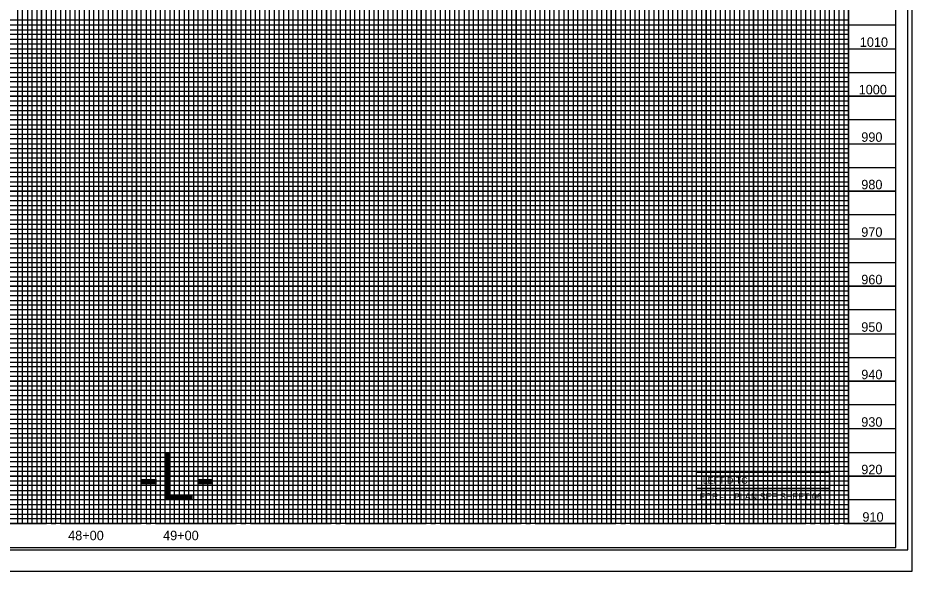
# Model space of a CAD drawing. Extents: x 1263639 to 1265460, y 747271 to 748371.
# Drawn here: x 1264381 to 1265323, y 747271 to 747853 of the extents above; entities that cross this region are included whole.
import ezdxf

# ---------------------------------------------------------------- set-up
doc = ezdxf.new("R2010")
doc.units = 0
for name, color, linetype in [('Pattern 1', 7, 'Continuous'), ('Pattern 2', 7, 'Continuous'), ('Prop Approach Slab', 7, 'Continuous'), ('Prop Drainage Structure Bridge Opening', 7, 'Continuous'), ('Prop Erosion Rip Rap Single Stone CELL', 7, 'Continuous'), ('Prop Grid Mask', 7, 'Continuous'), ('Prop Horizontal Alignment Curve and Spiral Data', 7, 'Continuous'), ('Prop Paved Shoulder', 7, 'Continuous'), ('Prop PFL Text', 7, 'Continuous'), ('Prop Terminator CELL', 7, 'Continuous'), ('Prop Vertical Profile Strip Grade', 7, 'Continuous'), ('Prop VPI Label', 7, 'Continuous'), ('Sheet Border Standard 30in CELL', 7, 'Continuous'), ('Sheet Profile Grid Middle CELL', 7, 'Continuous'), ('Sheet Sticker Exception Certification CELL', 7, 'Continuous')]:
    doc.layers.add(name, color=color, linetype=linetype)

msp = doc.modelspace()

# ---------------------------------------------------------------- linework, layer by layer
at = {"layer": 'Pattern 1'}
for points in [[(1264355.75, 747320.74), (1264405.75, 747320.74), (1264405.75, 748345.74)], [(1264455.75, 748345.74), (1264455.75, 747320.74), (1264505.75, 747320.74), (1264505.75, 748345.74)], [(1264555.75, 748345.74), (1264555.75, 747320.74), (1264605.75, 747320.74), (1264605.75, 748345.74)], [(1264655.75, 748345.74), (1264655.75, 747320.74), (1264705.75, 747320.74), (1264705.75, 748345.74)], [(1264755.75, 748345.74), (1264755.75, 747320.74), (1264805.75, 747320.74), (1264805.75, 748345.74)], [(1264855.75, 748345.74), (1264855.75, 747320.74), (1264905.75, 747320.74), (1264905.75, 748345.74)], [(1264955.75, 748345.74), (1264955.75, 747320.74), (1265005.75, 747320.74), (1265005.75, 748295.74)], [(1265055.75, 748295.74), (1265055.75, 747320.74), (1265105.75, 747320.74), (1265105.75, 748295.74)], [(1265155.75, 748184.69), (1265155.75, 747320.74), (1265205.75, 747320.74), (1265205.75, 748184.69)], [(1265255.75, 748184.69), (1265255.75, 747320.74), (1265305.75, 747320.74)], [(1265305.75, 747770.74), (1263805.75, 747770.74), (1263805.75, 747820.74), (1265305.75, 747820.74)], [(1265305.75, 747670.74), (1263805.75, 747670.74), (1263805.75, 747720.74), (1265305.75, 747720.74)], [(1265305.75, 747570.74), (1263805.75, 747570.74), (1263805.75, 747620.74), (1265305.75, 747620.74)], [(1265305.75, 747470.74), (1263805.75, 747470.74), (1263805.75, 747520.74), (1265305.75, 747520.74)], [(1265305.75, 747370.74), (1263805.75, 747370.74), (1263805.75, 747420.74), (1265305.75, 747420.74)]]:
    msp.add_lwpolyline(points, dxfattribs=at)
at = {"layer": 'Pattern 2'}
for points in [[(1264330.75, 747320.74), (1264380.75, 747320.74), (1264380.75, 748345.74)], [(1264430.75, 748345.74), (1264430.75, 747320.74), (1264480.75, 747320.74), (1264480.75, 748345.74)], [(1264530.75, 748345.74), (1264530.75, 747320.74), (1264580.75, 747320.74), (1264580.75, 748345.74)], [(1264630.75, 748345.74), (1264630.75, 747320.74), (1264680.75, 747320.74), (1264680.75, 748345.74)], [(1264730.75, 748345.74), (1264730.75, 747320.74), (1264780.75, 747320.74), (1264780.75, 748345.74)], [(1264830.75, 748345.74), (1264830.75, 747320.74), (1264880.75, 747320.74), (1264880.75, 748345.74)], [(1264930.75, 748345.74), (1264930.75, 747320.74), (1264980.75, 747320.74), (1264980.75, 748345.74)], [(1265030.75, 748295.74), (1265030.75, 747320.74), (1265080.75, 747320.74), (1265080.75, 748295.74)], [(1265130.75, 748184.69), (1265130.75, 747320.74), (1265180.75, 747320.74), (1265180.75, 748184.69)], [(1265230.75, 748184.69), (1265230.75, 747320.74)], [(1265305.75, 747845.74), (1263805.75, 747845.74), (1263805.75, 747795.74), (1265305.75, 747795.74)], [(1265305.75, 747745.74), (1263805.75, 747745.74), (1263805.75, 747695.74), (1265305.75, 747695.74)], [(1265305.75, 747645.74), (1263805.75, 747645.74), (1263805.75, 747595.74), (1265305.75, 747595.74)], [(1265305.75, 747545.74), (1263805.75, 747545.74), (1263805.75, 747495.74), (1265305.75, 747495.74)], [(1265305.75, 747445.74), (1263805.75, 747445.74), (1263805.75, 747395.74), (1265305.75, 747395.74)], [(1265305.75, 747345.74), (1263805.75, 747345.74)]]:
    msp.add_lwpolyline(points, dxfattribs=at)
at = {"layer": 'Prop Approach Slab'}
msp.add_line((1265157.4, 747366.24), (1265230.39, 747366.24), dxfattribs=at)
at = {"layer": 'Prop Drainage Structure Bridge Opening'}
msp.add_line((1263638.75, 747270.74), (1265322.75, 747270.74), dxfattribs=at)
at = {"layer": 'Prop Erosion Rip Rap Single Stone CELL'}
msp.add_lwpolyline([(1265095.75, 747374.74), (1265235.75, 747374.74), (1265235.75, 747357.74), (1265095.75, 747357.74)], close=True, dxfattribs=at)
at = {"layer": 'Prop Grid Mask'}
msp.add_lwpolyline([(1263855.75, 748345.74), (1265105.7, 748345.74), (1265105.75, 747320.74), (1263855.75, 747320.74)], close=True, dxfattribs=at)
at = {"layer": 'Prop Paved Shoulder'}
msp.add_line((1265305.75, 747320.74), (1263805.75, 747320.74), dxfattribs=at)
msp.add_lwpolyline([(1265305.75, 748345.74), (1263805.75, 748345.74), (1263805.75, 747295.74), (1265305.75, 747295.74)], close=True, dxfattribs=at)
at = {"layer": 'Prop PFL Text'}
for p, q in [((1264405.75, 748345.74), (1264405.75, 747320.74)), ((1264455.75, 748345.74), (1264455.75, 747320.74)), ((1264505.75, 748345.74), (1264505.75, 747320.74)), ((1264555.75, 748345.74), (1264555.75, 747320.74)), ((1264605.75, 748345.74), (1264605.75, 747320.74)), ((1264655.75, 748345.74), (1264655.75, 747320.74)), ((1264705.75, 748345.74), (1264705.75, 747320.74)), ((1264755.75, 748345.74), (1264755.75, 747320.74)), ((1264805.75, 748345.74), (1264805.75, 747320.74)), ((1264855.75, 748345.74), (1264855.75, 747320.74)), ((1264905.75, 748345.74), (1264905.75, 747320.74)), ((1264955.75, 748345.74), (1264955.75, 747320.74)), ((1265005.75, 748345.74), (1265005.75, 747320.74)), ((1265055.75, 748295.74), (1265055.75, 747320.74)), ((1265105.75, 747320.74), (1265105.75, 748208.19)), ((1265155.75, 747320.74), (1265155.75, 748184.69)), ((1265205.75, 747320.74), (1265205.75, 748184.69)), ((1265255.75, 747320.74), (1265255.75, 748184.69)), ((1263805.75, 747820.74), (1265305.75, 747820.74)), ((1263805.75, 747770.74), (1265305.75, 747770.74)), ((1263805.75, 747720.74), (1265305.75, 747720.74)), ((1263805.75, 747670.74), (1265305.75, 747670.74)), ((1263805.75, 747620.74), (1265305.75, 747620.74)), ((1263805.75, 747570.74), (1265305.75, 747570.74)), ((1263805.75, 747520.74), (1265305.75, 747520.74)), ((1263805.75, 747470.74), (1265305.75, 747470.74)), ((1263805.75, 747420.74), (1265305.75, 747420.74)), ((1263805.75, 747370.74), (1265305.75, 747370.74))]:
    msp.add_line(p, q, dxfattribs=at)
at = {"layer": 'Prop Terminator CELL'}
msp.add_lwpolyline([(1265318.25, 748348.29), (1263651.75, 748348.29), (1263651.75, 747293.19), (1265318.25, 747293.19)], close=True, dxfattribs=at)
at = {"layer": 'Prop VPI Label'}
msp.add_lwpolyline([(1265322.75, 748370.74), (1263638.75, 748370.74), (1263638.75, 747270.74), (1265322.75, 747270.74)], close=True, dxfattribs=at)
at = {"layer": 'Sheet Profile Grid Middle CELL'}
msp.add_lwpolyline([(1265095.75, 747357.74), (1265235.75, 747357.74), (1265235.75, 747340.74), (1265095.75, 747340.74)], close=True, dxfattribs=at)
at = {"layer": 'Sheet Sticker Exception Certification CELL'}
for points in [[(1264385.75, 747320.74), (1264385.75, 748345.74)], [(1264390.75, 748345.74), (1264390.75, 747320.74), (1264395.75, 747320.74), (1264395.75, 748345.74)], [(1264400.75, 748345.74), (1264400.75, 747320.74), (1264410.75, 747320.74), (1264410.75, 748345.74)], [(1264415.75, 748345.74), (1264415.75, 747320.74), (1264415.75, 747320.74), (1264420.75, 747320.74), (1264420.75, 748345.74)], [(1264425.75, 748345.74), (1264425.75, 747320.74), (1264435.75, 747320.74), (1264435.75, 748345.74)], [(1264440.75, 748345.74), (1264440.75, 747320.74), (1264445.75, 747320.74), (1264445.75, 748345.74)], [(1264450.75, 748345.74), (1264450.75, 747320.74), (1264460.75, 747320.74), (1264460.75, 748345.74)], [(1264465.75, 748345.74), (1264465.75, 747320.74), (1264470.75, 747320.74), (1264470.75, 748345.74)], [(1264475.75, 748345.74), (1264475.75, 747320.74), (1264485.75, 747320.74), (1264485.75, 748345.74)], [(1264490.75, 748345.74), (1264490.75, 747320.74), (1264495.75, 747320.74), (1264495.75, 748345.74)], [(1264500.75, 748345.74), (1264500.75, 747320.74), (1264510.75, 747320.74), (1264510.75, 748345.74)], [(1264515.75, 748345.74), (1264515.75, 747320.74), (1264520.75, 747320.74), (1264520.75, 748345.74)], [(1264525.75, 748345.74), (1264525.75, 747320.74), (1264535.75, 747320.74), (1264535.75, 748345.74)], [(1264540.75, 748345.74), (1264540.75, 747320.74), (1264545.75, 747320.74), (1264545.75, 748345.74)], [(1264550.75, 748345.74), (1264550.75, 747320.74), (1264560.75, 747320.74), (1264560.75, 748345.74)], [(1264565.75, 748345.74), (1264565.75, 747320.74)], [(1264565.75, 747320.74), (1264570.75, 747320.74), (1264570.75, 748345.14)], [(1264575.75, 748345.14), (1264575.75, 747320.74), (1264585.75, 747320.74), (1264585.75, 748345.74)], [(1264590.75, 748345.74), (1264590.75, 747320.74), (1264595.75, 747320.74), (1264595.75, 748345.74)], [(1264600.75, 748345.74), (1264600.75, 747320.74), (1264610.75, 747320.74), (1264610.75, 748345.74)], [(1264615.75, 748345.74), (1264615.75, 747320.74), (1264620.75, 747320.74), (1264620.75, 748345.74)], [(1264625.75, 748345.74), (1264625.75, 747320.74), (1264635.75, 747320.74), (1264635.75, 748345.74)], [(1264640.75, 748345.74), (1264640.75, 747320.74), (1264645.75, 747320.74), (1264645.75, 748345.74)], [(1264650.75, 748345.74), (1264650.75, 747320.74), (1264660.75, 747320.74), (1264660.75, 748345.74)], [(1264665.75, 748345.74), (1264665.75, 747320.74), (1264670.75, 747320.74), (1264670.75, 748345.74)], [(1264675.75, 748345.74), (1264675.75, 747320.74), (1264685.75, 747320.74), (1264685.75, 748345.74)], [(1264690.75, 748345.74), (1264690.75, 747320.74), (1264695.75, 747320.74), (1264695.75, 748345.74)], [(1264700.75, 748345.74), (1264700.75, 747320.74), (1264710.75, 747320.74), (1264710.75, 748345.74)], [(1264715.75, 748345.74), (1264715.75, 747320.74), (1264720.75, 747320.74), (1264720.75, 748345.74)], [(1264725.75, 748345.74), (1264725.75, 747320.74), (1264735.75, 747320.74), (1264735.75, 748345.74)], [(1264740.75, 748345.74), (1264740.75, 747320.74), (1264745.75, 747320.74), (1264745.75, 748345.74)], [(1264750.75, 748345.74), (1264750.75, 747320.74), (1264760.75, 747320.74), (1264760.75, 748345.74)], [(1264765.75, 748345.74), (1264765.75, 747320.74), (1264770.75, 747320.74), (1264770.75, 748345.74)], [(1264775.75, 748345.74), (1264775.75, 747320.74), (1264785.75, 747320.74), (1264785.75, 748345.74)], [(1264790.75, 748345.74), (1264790.75, 747320.74), (1264795.75, 747320.74), (1264795.75, 748345.74)], [(1264800.75, 748345.74), (1264800.75, 747320.74), (1264810.75, 747320.74), (1264810.75, 748345.74)], [(1264815.75, 748345.74), (1264815.75, 747320.74), (1264820.75, 747320.74), (1264820.75, 748345.74)], [(1264825.75, 748345.74), (1264825.75, 747320.74), (1264835.75, 747320.74), (1264835.75, 748345.74)], [(1264840.75, 748345.74), (1264840.75, 747320.74), (1264845.75, 747320.74), (1264845.75, 748345.74)], [(1264850.75, 748345.74), (1264850.75, 747320.74), (1264860.75, 747320.74), (1264860.75, 748345.74)], [(1264865.75, 748345.74), (1264865.75, 747320.74), (1264870.75, 747320.74), (1264870.75, 748345.74)], [(1264875.75, 748345.74), (1264875.75, 747320.74)], [(1264875.75, 747320.74), (1264885.75, 747320.74), (1264885.75, 748345.74)], [(1264890.75, 748345.74), (1264890.75, 747320.74), (1264895.75, 747320.74), (1264895.75, 748345.74)], [(1264900.75, 748345.74), (1264900.75, 747320.74), (1264910.75, 747320.74), (1264910.75, 748345.74)], [(1264915.75, 748345.74), (1264915.75, 747320.74), (1264920.75, 747320.74), (1264920.75, 748345.74)], [(1264925.75, 748345.74), (1264925.75, 747320.74), (1264935.75, 747320.74), (1264935.75, 748345.74)], [(1264940.75, 748345.74), (1264940.75, 747320.74), (1264945.75, 747320.74), (1264945.75, 748345.74)], [(1264950.75, 748345.74), (1264950.75, 747320.74), (1264960.75, 747320.74), (1264960.75, 748345.74)], [(1264965.75, 748345.74), (1264965.75, 747320.74), (1264970.75, 747320.74), (1264970.75, 748345.74)], [(1264975.75, 748345.74), (1264975.75, 747320.74), (1264985.75, 747320.74), (1264985.75, 748345.74)], [(1264990.75, 748345.74), (1264990.75, 747320.74), (1264995.75, 747320.74), (1264995.75, 748345.74)], [(1265000.75, 748345.74), (1265000.75, 747320.74), (1265010.75, 747320.74), (1265010.75, 748295.74)], [(1265015.75, 748295.74), (1265015.75, 747320.74), (1265020.75, 747320.74), (1265020.75, 748295.74)], [(1265025.75, 748295.74), (1265025.75, 747320.74), (1265035.75, 747320.74), (1265035.75, 748295.74)], [(1265040.75, 748295.74), (1265040.75, 747320.74), (1265045.75, 747320.74), (1265045.75, 748295.74)], [(1265050.75, 748295.74), (1265050.75, 747320.74), (1265060.75, 747320.74), (1265060.75, 748295.74)], [(1265065.75, 748295.74), (1265065.75, 747320.74), (1265070.75, 747320.74), (1265070.75, 748295.74)], [(1265075.75, 748295.74), (1265075.75, 747320.74), (1265085.75, 747320.74), (1265085.75, 748295.74)], [(1265090.75, 748295.74), (1265090.75, 747320.74), (1265095.75, 747320.74), (1265095.75, 748295.74)], [(1265100.75, 748295.74), (1265100.75, 747320.74), (1265110.75, 747320.74), (1265110.75, 748184.69)], [(1265115.75, 748184.69), (1265115.75, 747320.74), (1265120.75, 747320.74), (1265120.75, 748184.69)], [(1265125.75, 748184.69), (1265125.75, 747320.74), (1265135.75, 747320.74), (1265135.75, 748184.69)], [(1265140.75, 748184.69), (1265140.75, 747320.74), (1265145.75, 747320.74), (1265145.75, 748184.69)], [(1265150.75, 748184.69), (1265150.75, 747320.74), (1265160.75, 747320.74), (1265160.75, 748184.69)], [(1265165.75, 748184.69), (1265165.75, 747320.74), (1265170.75, 747320.74), (1265170.75, 748184.69)], [(1265175.75, 748184.69), (1265175.75, 747320.74), (1265185.75, 747320.74), (1265185.75, 748184.69)], [(1265190.75, 748184.69), (1265190.75, 747320.74)], [(1265190.75, 747320.74), (1265195.75, 747320.74), (1265195.75, 748184.69)], [(1265200.75, 748184.69), (1265200.75, 747320.74), (1265210.75, 747320.74), (1265210.75, 748184.69)], [(1265215.75, 748184.69), (1265215.75, 747320.74), (1265220.75, 747320.74), (1265220.75, 748184.69)], [(1265225.75, 748184.69), (1265225.75, 747320.74), (1265235.75, 747320.74), (1265235.75, 748184.69)], [(1265240.75, 748184.69), (1265240.75, 747320.74), (1265245.75, 747320.74), (1265245.75, 748184.69)], [(1265250.75, 748184.69), (1265250.75, 747320.74), (1265260.75, 747320.74)], [(1265255.75, 747850.74), (1263855.75, 747850.74), (1263855.75, 747840.74), (1265255.75, 747840.74)], [(1265255.75, 747835.74), (1263855.75, 747835.74), (1263855.75, 747830.74), (1265255.75, 747830.74)], [(1265255.75, 747825.74), (1263855.75, 747825.74)], [(1263855.75, 747815.74), (1265255.75, 747815.74)], [(1265255.75, 747810.74), (1263855.75, 747810.74), (1263855.75, 747805.74), (1265255.75, 747805.74)], [(1265255.75, 747800.74), (1263855.75, 747800.74), (1263855.75, 747790.74), (1265255.75, 747790.74)], [(1265255.75, 747785.74), (1263855.75, 747785.74), (1263855.75, 747780.74), (1265255.75, 747780.74)], [(1265255.75, 747775.74), (1263855.75, 747775.74), (1263855.75, 747765.74), (1265255.75, 747765.74)], [(1265255.75, 747760.74), (1263855.75, 747760.74), (1263855.75, 747755.74), (1265255.75, 747755.74)], [(1265255.75, 747750.74), (1263855.75, 747750.74), (1263855.75, 747740.74), (1265255.75, 747740.74)], [(1265255.75, 747735.74), (1263855.75, 747735.74), (1263855.75, 747730.74), (1265255.75, 747730.74)], [(1265255.75, 747725.74), (1263855.75, 747725.74), (1263855.75, 747715.74), (1265255.75, 747715.74)], [(1265255.75, 747710.74), (1263855.75, 747710.74), (1263855.75, 747705.74), (1265255.75, 747705.74)], [(1265255.75, 747700.74), (1263855.75, 747700.74), (1263855.75, 747690.74), (1265255.75, 747690.74)], [(1265255.75, 747685.74), (1263855.75, 747685.74), (1263855.75, 747680.74), (1265255.75, 747680.74)], [(1265255.75, 747675.74), (1263855.75, 747675.74), (1263855.75, 747665.74), (1265255.75, 747665.74)], [(1265255.75, 747660.74), (1263855.75, 747660.74), (1263855.75, 747655.74), (1265255.75, 747655.74)], [(1265255.75, 747650.74), (1263855.75, 747650.74), (1263855.75, 747640.74), (1265255.75, 747640.74)], [(1265255.75, 747635.74), (1263855.75, 747635.74), (1263855.75, 747630.74), (1265255.75, 747630.74)], [(1265255.75, 747625.74), (1263855.75, 747625.74), (1263855.75, 747615.74), (1265255.75, 747615.74)], [(1265255.75, 747610.74), (1263855.75, 747610.74), (1263855.75, 747605.74), (1265255.75, 747605.74)], [(1265255.75, 747600.74), (1263855.75, 747600.74), (1263855.75, 747590.74), (1265255.75, 747590.74)], [(1265255.75, 747585.74), (1263855.75, 747585.74), (1263855.75, 747580.74), (1265255.75, 747580.74)], [(1265255.75, 747575.74), (1263855.75, 747575.74), (1263855.75, 747565.74), (1265255.75, 747565.74)], [(1265255.75, 747560.74), (1263855.75, 747560.74), (1263855.75, 747555.74), (1265255.75, 747555.74)], [(1265255.75, 747550.74), (1263855.75, 747550.74), (1263855.75, 747540.74), (1265255.75, 747540.74)], [(1265255.75, 747535.74), (1263855.75, 747535.74), (1263855.75, 747530.74), (1265255.75, 747530.74)], [(1265255.75, 747525.74), (1263855.75, 747525.74)], [(1263855.75, 747515.74), (1265255.75, 747515.74)], [(1265255.75, 747510.74), (1263855.75, 747510.74), (1263855.75, 747505.74), (1265255.75, 747505.74)], [(1265255.75, 747500.74), (1263855.75, 747500.74)], [(1263855.75, 747490.74), (1265255.75, 747490.74)], [(1265255.75, 747485.74), (1263855.75, 747485.74), (1263855.75, 747480.74), (1265255.75, 747480.74)], [(1265255.75, 747475.74), (1263855.75, 747475.74), (1263855.75, 747465.74), (1265255.75, 747465.74)], [(1265255.75, 747460.74), (1263855.75, 747460.74), (1263855.75, 747455.74), (1265255.75, 747455.74)], [(1265255.75, 747450.74), (1263855.75, 747450.74), (1263855.75, 747440.74), (1265255.75, 747440.74)], [(1265255.75, 747435.74), (1263855.75, 747435.74), (1263855.75, 747430.74), (1265255.75, 747430.74)], [(1265255.75, 747425.74), (1263855.75, 747425.74), (1263855.75, 747415.74), (1265255.75, 747415.74)], [(1265255.75, 747410.74), (1263855.75, 747410.74), (1263855.75, 747405.74), (1265255.75, 747405.74)], [(1265255.75, 747400.74), (1263855.75, 747400.74), (1263855.75, 747390.74), (1265255.75, 747390.74)], [(1265255.75, 747385.74), (1263855.75, 747385.74), (1263855.75, 747380.74), (1265255.75, 747380.74)], [(1265255.75, 747375.74), (1263855.75, 747375.74), (1263855.75, 747365.74), (1265255.75, 747365.74)], [(1265255.75, 747360.74), (1263855.75, 747360.74), (1263855.75, 747355.74), (1265255.75, 747355.74)], [(1265255.75, 747350.74), (1263855.75, 747350.74), (1263855.75, 747340.74), (1265255.75, 747340.74)], [(1265255.75, 747335.74), (1263855.75, 747335.74), (1263855.75, 747330.74), (1265255.75, 747330.74)], [(1265255.75, 747325.74), (1263855.75, 747325.74)]]:
    msp.add_lwpolyline(points, dxfattribs=at)

# ---------------------------------------------------------------- texts
at = {"layer": 'Prop Erosion Rip Rap Single Stone CELL'}
for s, p in [('LEFT DITCH', (1265102.23, 747362.73)), ('FOR -L- PLAN SEE SHEET 06', (1265098.72, 747345.74))]:
    msp.add_text(s, height=7, dxfattribs=at).set_placement(p)
at = {"layer": 'Prop Horizontal Alignment Curve and Spiral Data'}
for s, p in [('48+00', (1264433.69, 747303.24)), ('49+00', (1264533.69, 747303.24))]:
    msp.add_text(s, height=10, dxfattribs=at).set_placement(p)
at = {"layer": 'Prop Vertical Profile Strip Grade'}
for s, p in [('1010', (1265267.63, 747822.74)), ('1000', (1265266.43, 747772.74)), ('990', (1265269.19, 747722.74)), ('980', (1265269.19, 747672.74)), ('970', (1265269.19, 747622.74)), ('960', (1265269.19, 747572.74)), ('950', (1265269.19, 747522.74)), ('940', (1265269.19, 747472.74)), ('930', (1265269.19, 747422.74)), ('920', (1265269.19, 747372.74)), ('910', (1265270.38, 747322.74))]:
    msp.add_text(s, height=10, dxfattribs=at).set_placement(p)
at = {"layer": 'Sheet Border Standard 30in CELL'}
msp.add_text('-L-', height=50, dxfattribs=at).set_placement((1264507.65, 747345.74))

doc.saveas('drawing.dxf')
